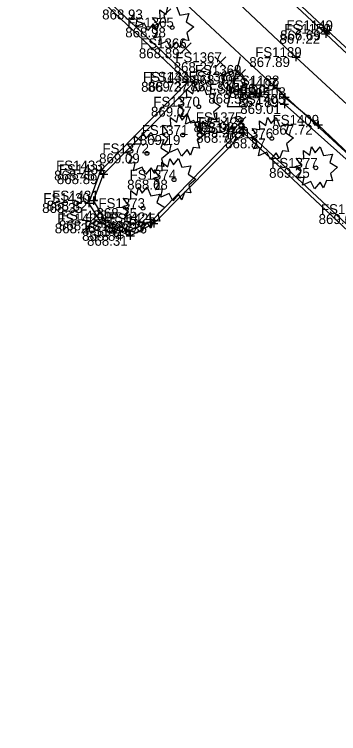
# Model space of a CAD drawing. Extents: x 1479420 to 1479833, y 379731 to 380103.
# Drawn here: x 1479671.7 to 1479710.9, y 379733.1 to 379820.1 of the extents above; entities that cross this region are included whole.
import ezdxf

# ---------------------------------------------------------------- set-up
doc = ezdxf.new("R2010")
doc.units = 0
for name, color, linetype in [('LT_X_Poles', 7, 'Continuous'), ('PV_X_Curb', 7, 'Continuous'), ('PV_X_Walk', 7, 'Continuous'), ('RD_X_Wall', 7, 'Continuous'), ('SV_X_Break_Lines', 7, 'Continuous'), ('SV_X_Random_Point', 7, 'Continuous'), ('SV_X_Shot_Marker', 7, 'Continuous'), ('SV_X_Text_Elevation', 7, 'Continuous'), ('SV_X_Text_Name', 7, 'Continuous'), ('VG_X_Cells', 7, 'Continuous')]:
    doc.layers.add(name, color=color, linetype=linetype)

msp = doc.modelspace()

# ---------------------------------------------------------------- linework, layer by layer
at = {"layer": 'LT_X_Poles'}
msp.add_lwpolyline([(1479699.003, 379814.915), (1479697.428, 379808.93), (1479699.791, 379808.93)], dxfattribs=at)
msp.add_circle((1479698.216, 379811.961), 1.3, dxfattribs=at)
at = {"layer": 'PV_X_Curb'}
for points in [[(1479752.341, 379756.82), (1479734.895, 379773.493), (1479717.229, 379789.662), (1479699.298, 379806.401), (1479688.16, 379794.934), (1479685.526, 379793.897), (1479682.733, 379795.157), (1479681.263, 379797.549), (1479682.493, 379800.746), (1479693.462, 379811.911), (1479675.554, 379828.75), (1479655.832, 379847.057), (1479640.191, 379861.808), (1479628.558, 379849), (1479624.614, 379847.663), (1479622.46, 379848.585), (1479618.996, 379850.857), (1479611.825, 379854.437), (1479601.319, 379856.891), (1479590.521, 379858.038)], [(1479751.933, 379756.628), (1479734.447, 379772.976), (1479716.701, 379789.463), (1479699.4, 379805.742), (1479688.561, 379794.786), (1479685.717, 379793.294), (1479682.291, 379794.8), (1479680.73, 379797.254), (1479682.169, 379801.189), (1479692.652, 379811.907), (1479675.183, 379828.391), (1479655.51, 379846.682), (1479640.151, 379860.926), (1479629.134, 379848.869), (1479624.571, 379847.215), (1479622.228, 379847.911), (1479618.757, 379850.398), (1479611.519, 379853.97), (1479601.347, 379856.369), (1479590.364, 379857.442)], [(1479667.239, 379857.122), (1479681.024, 379844.208), (1479695.135, 379830.978), (1479709.331, 379817.708), (1479723.729, 379804.193), (1479729.719, 379798.6), (1479748.963, 379780.548), (1479759.065, 379771.485), (1479760.185, 379770.473), (1479774.837, 379758.13), (1479787.835, 379747.16), (1479799.962, 379737.109), (1479801.3, 379736.045)], [(1479667.529, 379857.521), (1479681.356, 379844.557), (1479695.384, 379831.416), (1479709.512, 379818.131), (1479724.003, 379804.728), (1479730.662, 379798.272), (1479750.68, 379779.69), (1479759.253, 379771.893), (1479760.555, 379770.78), (1479775.03, 379758.526), (1479788.183, 379747.585), (1479800.537, 379737.251), (1479801.677, 379736.292)]]:
    msp.add_lwpolyline(points, dxfattribs=at)
at = {"layer": 'PV_X_Walk'}
for points in [[(1479760.141, 379765.373), (1479756.862, 379768.221), (1479747.096, 379776.51), (1479736.047, 379786.698), (1479722.324, 379799.574), (1479705.728, 379814.894), (1479685.769, 379833.708), (1479660.411, 379857.395)], [(1479801.031, 379735.954), (1479794.804, 379736.123), (1479792.191, 379733.142), (1479782.769, 379741.06), (1479767.055, 379754.294), (1479759.061, 379761.026), (1479757.309, 379762.481), (1479754.256, 379765.105), (1479744.261, 379773.561), (1479732.859, 379783.688), (1479719.35, 379796.384), (1479703.027, 379811.462), (1479682.443, 379830.686), (1479657.296, 379854.468)]]:
    msp.add_lwpolyline(points, dxfattribs=at)
at = {"layer": 'RD_X_Wall'}
msp.add_lwpolyline([(1479756.217, 379756.164), (1479757.574, 379758.774), (1479757.809, 379760.44), (1479756.184, 379761.773), (1479753.461, 379764.22), (1479749.272, 379767.89), (1479743.159, 379773.169), (1479734.585, 379781.475), (1479724.018, 379791.188), (1479717.004, 379797.909), (1479704.341, 379809.227)], dxfattribs=at)
at = {"layer": 'SV_X_Break_Lines'}
msp.add_lwpolyline([(1479700.791, 379810.474), (1479703.421, 379811.158), (1479704.398, 379810.048), (1479708.429, 379806.713), (1479717.526, 379798.095), (1479729.107, 379786.809), (1479738.375, 379778.753), (1479747.99, 379770.392), (1479758.225, 379761.836), (1479757.039, 379755.523)], dxfattribs=at)
at = {"layer": 'SV_X_Random_Point'}
for p, q in [((1479691.739, 379815.289), (1479693.073, 379816.624)), ((1479691.739, 379816.624), (1479693.073, 379815.289)), ((1479695.916, 379813.611), (1479697.25, 379814.946)), ((1479695.916, 379814.946), (1479697.25, 379813.611)), ((1479698.288, 379812.077), (1479699.622, 379813.412)), ((1479698.288, 379813.412), (1479699.622, 379812.077)), ((1479698.353, 379806.36), (1479699.687, 379807.695)), ((1479698.353, 379807.695), (1479699.687, 379806.36))]:
    msp.add_line(p, q, dxfattribs=at)
at = {"layer": 'SV_X_Shot_Marker'}
for p, q in [((1479709.512, 379818.631), (1479709.512, 379817.631)), ((1479708.831, 379817.708), (1479709.831, 379817.708)), ((1479709.012, 379818.131), (1479710.012, 379818.131)), ((1479709.331, 379818.208), (1479709.331, 379817.208)), ((1479709.331, 379817.708), (1479709.331, 379817.708)), ((1479709.512, 379818.131), (1479709.512, 379818.131)), ((1479705.728, 379815.394), (1479705.728, 379814.394)), ((1479705.228, 379814.894), (1479706.228, 379814.894)), ((1479705.728, 379814.894), (1479705.728, 379814.894)), ((1479692.152, 379811.907), (1479693.152, 379811.907)), ((1479692.652, 379812.407), (1479692.652, 379811.407)), ((1479692.652, 379811.907), (1479692.652, 379811.907)), ((1479692.962, 379811.911), (1479693.962, 379811.911)), ((1479693.462, 379812.411), (1479693.462, 379811.411)), ((1479693.462, 379811.911), (1479693.462, 379811.911)), ((1479703.027, 379811.962), (1479703.027, 379810.962)), ((1479703.421, 379811.658), (1479703.421, 379810.658)), ((1479700.791, 379810.974), (1479700.791, 379809.974)), ((1479702.527, 379811.462), (1479703.527, 379811.462)), ((1479702.921, 379811.158), (1479703.921, 379811.158)), ((1479703.027, 379811.462), (1479703.027, 379811.462)), ((1479703.421, 379811.158), (1479703.421, 379811.158)), ((1479700.291, 379810.474), (1479701.291, 379810.474)), ((1479700.791, 379810.474), (1479700.791, 379810.474)), ((1479703.898, 379810.048), (1479704.898, 379810.048)), ((1479704.398, 379810.548), (1479704.398, 379809.548)), ((1479704.398, 379810.048), (1479704.398, 379810.048)), ((1479703.841, 379809.227), (1479704.841, 379809.227)), ((1479704.341, 379809.727), (1479704.341, 379808.727)), ((1479704.341, 379809.227), (1479704.341, 379809.227)), ((1479698.798, 379806.401), (1479699.798, 379806.401)), ((1479699.298, 379806.901), (1479699.298, 379805.901)), ((1479699.298, 379806.401), (1479699.298, 379806.401)), ((1479707.929, 379806.713), (1479708.929, 379806.713)), ((1479708.429, 379807.213), (1479708.429, 379806.213)), ((1479708.429, 379806.713), (1479708.429, 379806.713)), ((1479698.9, 379805.742), (1479699.9, 379805.742)), ((1479699.4, 379806.242), (1479699.4, 379805.242)), ((1479699.4, 379805.742), (1479699.4, 379805.742)), ((1479681.669, 379801.189), (1479682.669, 379801.189)), ((1479682.169, 379801.689), (1479682.169, 379800.689)), ((1479682.169, 379801.189), (1479682.169, 379801.189)), ((1479682.493, 379801.246), (1479682.493, 379800.246)), ((1479681.993, 379800.746), (1479682.993, 379800.746)), ((1479682.493, 379800.746), (1479682.493, 379800.746)), ((1479680.73, 379797.754), (1479680.73, 379796.754)), ((1479681.263, 379798.049), (1479681.263, 379797.049)), ((1479680.23, 379797.254), (1479681.23, 379797.254)), ((1479680.73, 379797.254), (1479680.73, 379797.254)), ((1479680.763, 379797.549), (1479681.763, 379797.549)), ((1479681.263, 379797.549), (1479681.263, 379797.549)), ((1479682.233, 379795.157), (1479683.233, 379795.157)), ((1479682.291, 379795.3), (1479682.291, 379794.3)), ((1479682.733, 379795.657), (1479682.733, 379794.657)), ((1479682.733, 379795.157), (1479682.733, 379795.157)), ((1479688.16, 379795.434), (1479688.16, 379794.434)), ((1479688.561, 379795.286), (1479688.561, 379794.286)), ((1479681.791, 379794.8), (1479682.791, 379794.8)), ((1479682.291, 379794.8), (1479682.291, 379794.8)), ((1479685.526, 379794.397), (1479685.526, 379793.397)), ((1479687.66, 379794.934), (1479688.66, 379794.934)), ((1479688.061, 379794.786), (1479689.061, 379794.786)), ((1479688.16, 379794.934), (1479688.16, 379794.934)), ((1479688.561, 379794.786), (1479688.561, 379794.786)), ((1479685.026, 379793.897), (1479686.026, 379793.897)), ((1479685.526, 379793.897), (1479685.526, 379793.897)), ((1479685.717, 379793.794), (1479685.717, 379792.794)), ((1479685.217, 379793.294), (1479686.217, 379793.294)), ((1479685.717, 379793.294), (1479685.717, 379793.294))]:
    msp.add_line(p, q, dxfattribs=at)
at = {"layer": 'VG_X_Cells'}
for points in [[(1479690.613, 379820.712), (1479689.757, 379819.977), (1479690.007, 379819.063), (1479689.253, 379819.132), (1479688.928, 379818.218), (1479688.5, 379818.91), (1479687.822, 379818.093), (1479687.393, 379818.98), (1479686.373, 379818.55), (1479686.565, 379819.492), (1479685.753, 379819.408), (1479686.227, 379820.198)], [(1479691.298, 379821.026), (1479691.713, 379819.972), (1479692.805, 379820.152), (1479692.466, 379819.141), (1479693.411, 379818.546), (1479692.555, 379817.811), (1479692.805, 379816.897), (1479692.051, 379816.966), (1479691.726, 379816.052), (1479691.298, 379816.744), (1479690.62, 379815.927), (1479690.191, 379816.814), (1479689.171, 379816.384), (1479689.363, 379817.326), (1479688.551, 379817.242), (1479689.025, 379818.032), (1479688.256, 379818.601), (1479688.995, 379818.864), (1479688.388, 379819.667), (1479689.32, 379819.557), (1479689.29, 379820.596), (1479690.043, 379820.027), (1479690.25, 379821.012)], [(1479693.906, 379810.711), (1479694.511, 379811.446), (1479694.926, 379810.393), (1479696.018, 379810.573), (1479695.679, 379809.561), (1479696.624, 379808.966), (1479695.768, 379808.231), (1479696.018, 379807.318), (1479695.264, 379807.386), (1479694.939, 379806.473), (1479694.511, 379807.164), (1479693.833, 379806.348), (1479693.404, 379807.234), (1479692.384, 379806.804), (1479692.576, 379807.746), (1479691.764, 379807.663), (1479692.238, 379808.453), (1479691.469, 379809.021), (1479692.208, 379809.284), (1479691.601, 379810.088), (1479692.533, 379809.978), (1479692.503, 379811.016), (1479693.256, 379810.448), (1479693.463, 379811.433), (1479693.906, 379810.711)], [(1479691.972, 379807.288), (1479692.577, 379808.023), (1479692.992, 379806.969), (1479694.084, 379807.149), (1479693.745, 379806.138), (1479694.69, 379805.543), (1479693.834, 379804.808), (1479694.084, 379803.894), (1479693.33, 379803.963), (1479693.005, 379803.049), (1479692.577, 379803.741), (1479691.899, 379802.924), (1479691.47, 379803.811), (1479690.45, 379803.381), (1479690.642, 379804.323), (1479689.83, 379804.239), (1479690.304, 379805.029), (1479689.535, 379805.598), (1479690.274, 379805.861), (1479689.667, 379806.664), (1479690.599, 379806.554), (1479690.569, 379807.593), (1479691.322, 379807.024), (1479691.529, 379808.009), (1479691.972, 379807.288)], [(1479702.73, 379806.878), (1479703.335, 379807.613), (1479703.75, 379806.559), (1479704.842, 379806.739), (1479704.503, 379805.728), (1479705.448, 379805.133), (1479704.592, 379804.398), (1479704.842, 379803.484), (1479704.088, 379803.553), (1479703.763, 379802.639), (1479703.335, 379803.331), (1479702.657, 379802.514), (1479702.228, 379803.401), (1479701.208, 379802.971), (1479701.4, 379803.913), (1479700.588, 379803.829), (1479701.062, 379804.619), (1479700.293, 379805.188), (1479701.032, 379805.451), (1479700.425, 379806.254), (1479701.357, 379806.144), (1479701.327, 379807.183), (1479702.08, 379806.614), (1479702.287, 379807.599), (1479702.73, 379806.878)], [(1479687.646, 379805.067), (1479688.251, 379805.802), (1479688.666, 379804.749), (1479689.758, 379804.929), (1479689.419, 379803.917), (1479690.364, 379803.322), (1479689.508, 379802.587), (1479689.758, 379801.674), (1479689.004, 379801.742), (1479688.679, 379800.829), (1479688.251, 379801.521), (1479687.573, 379800.704), (1479687.144, 379801.591), (1479686.124, 379801.161), (1479686.316, 379802.102), (1479685.504, 379802.019), (1479685.978, 379802.809), (1479685.209, 379803.377), (1479685.948, 379803.641), (1479685.341, 379804.444), (1479686.273, 379804.334), (1479686.243, 379805.372), (1479686.996, 379804.804), (1479687.203, 379805.789), (1479687.646, 379805.067)], [(1479708.046, 379803.323), (1479708.651, 379804.058), (1479709.066, 379803.004), (1479710.158, 379803.184), (1479709.819, 379802.173), (1479710.764, 379801.578), (1479709.908, 379800.843), (1479710.158, 379799.929), (1479709.404, 379799.998), (1479709.079, 379799.084), (1479708.651, 379799.776), (1479707.973, 379798.959), (1479707.544, 379799.846), (1479706.524, 379799.416), (1479706.716, 379800.358), (1479705.904, 379800.274), (1479706.378, 379801.064), (1479705.609, 379801.633), (1479706.348, 379801.896), (1479705.741, 379802.699), (1479706.673, 379802.589), (1479706.643, 379803.628), (1479707.396, 379803.059), (1479707.603, 379804.044), (1479708.046, 379803.323)], [(1479690.923, 379801.895), (1479691.528, 379802.63), (1479691.943, 379801.576), (1479693.035, 379801.756), (1479692.696, 379800.745), (1479693.641, 379800.15), (1479692.785, 379799.415), (1479693.035, 379798.501), (1479692.281, 379798.57), (1479691.956, 379797.656), (1479691.528, 379798.348), (1479690.85, 379797.531), (1479690.421, 379798.418), (1479689.401, 379797.988), (1479689.593, 379798.93), (1479688.781, 379798.846), (1479689.255, 379799.636), (1479688.486, 379800.205), (1479689.225, 379800.468), (1479688.618, 379801.271), (1479689.55, 379801.161), (1479689.52, 379802.2), (1479690.273, 379801.631), (1479690.48, 379802.616), (1479690.923, 379801.895)], [(1479687.172, 379798.455), (1479687.777, 379799.19), (1479688.192, 379798.136), (1479689.284, 379798.316), (1479688.945, 379797.305), (1479689.89, 379796.71), (1479689.034, 379795.975), (1479689.284, 379795.061), (1479688.53, 379795.13), (1479688.205, 379794.216), (1479687.777, 379794.908), (1479687.099, 379794.091), (1479686.67, 379794.978), (1479685.65, 379794.548), (1479685.842, 379795.49), (1479685.03, 379795.406), (1479685.504, 379796.196), (1479684.735, 379796.765), (1479685.474, 379797.028), (1479684.867, 379797.831), (1479685.799, 379797.721), (1479685.769, 379798.76), (1479686.522, 379798.191), (1479686.729, 379799.176), (1479687.172, 379798.455)]]:
    msp.add_lwpolyline(points, dxfattribs=at)
for centre in [(1479690.777, 379818.481), (1479693.99, 379808.902), (1479692.056, 379805.478), (1479702.814, 379805.068), (1479687.73, 379803.258), (1479708.13, 379801.513), (1479691.007, 379800.085), (1479687.256, 379796.645)]:
    msp.add_circle(centre, 0.23, dxfattribs=at)

# ---------------------------------------------------------------- texts
at = {"layer": 'SV_X_Text_Elevation'}
for s, p in [('868.93', (1479682.321, 379819.447)), ('868.98', (1479685.109, 379817.281)), ('867.22', (1479703.738, 379816.508)), ('866.69', (1479703.824, 379816.931)), ('868.89', (1479686.756, 379814.757)), ('868.27', (1479690.961, 379813.079)), ('867.89', (1479700.097, 379813.694)), ('868.09', (1479693.192, 379811.545)), ('868.73', (1479687.03, 379810.707)), ('869.27', (1479687.821, 379810.711)), ('868.31', (1479692.99, 379810.762)), ('868.00', (1479697.169, 379810.262)), ('868.05', (1479697.667, 379809.958)), ('868.58', (1479695.141, 379809.274)), ('867.89', (1479698.767, 379808.848)), ('869.01', (1479699.002, 379808.027)), ('869.07', (1479688.218, 379807.701)), ('868.93', (1479693.361, 379805.827)), ('869.27', (1479693.657, 379805.201)), ('867.72', (1479702.836, 379805.513)), ('868.70', (1479693.674, 379804.542)), ('869.19', (1479686.861, 379804.278)), ('868.87', (1479697.174, 379803.868)), ('869.09', (1479681.949, 379802.057)), ('868.45', (1479676.519, 379799.989)), ('869.25', (1479702.49, 379800.313)), ('868.89', (1479676.843, 379799.546)), ('868.68', (1479685.339, 379798.885)), ('868.35', (1479675.071, 379796.054)), ('868.82', (1479675.632, 379796.349)), ('868.75', (1479681.635, 379795.445)), ('868.78', (1479677.102, 379793.957)), ('869.65', (1479708.471, 379794.721)), ('868.26', (1479676.594, 379793.6)), ('868.95', (1479682.501, 379793.734)), ('868.36', (1479682.826, 379793.586)), ('868.84', (1479679.895, 379792.697)), ('868.31', (1479680.491, 379792.094))]:
    msp.add_text(s, height=1.2, dxfattribs=at).set_placement(p)
at = {"layer": 'SV_X_Text_Name'}
for s, p in [('FS1365', (1479685.355, 379818.481)), ('FS1150', (1479704.315, 379817.708)), ('FS1149', (1479704.581, 379818.131)), ('FS1366', (1479686.908, 379815.957)), ('FS1189', (1479700.807, 379814.894)), ('FS1367', (1479691.16, 379814.279)), ('FS1369', (1479693.523, 379812.745)), ('FS1434', (1479687.248, 379811.907)), ('FS1435', (1479688.049, 379811.911)), ('FS1368', (1479692.784, 379811.962)), ('FS1188', (1479698.106, 379811.462)), ('FS1406', (1479695.208, 379810.474)), ('FS1407', (1479697.913, 379811.158)), ('FS1408', (1479698.881, 379810.048)), ('FS1370', (1479688.502, 379808.901)), ('FS1405', (1479698.833, 379809.227)), ('FS1375', (1479693.635, 379807.027)), ('FS1423', (1479693.923, 379806.401)), ('FS1409', (1479702.912, 379806.713)), ('FS1371', (1479687.106, 379805.478)), ('FS1422', (1479694.034, 379805.742)), ('FS1376', (1479697.355, 379805.068)), ('FS1372', (1479682.356, 379803.257)), ('FS1433', (1479676.756, 379801.189)), ('FS1377', (1479702.746, 379801.513)), ('FS1432', (1479677.089, 379800.746)), ('FS1374', (1479685.633, 379800.085)), ('FS1431', (1479676.284, 379797.549)), ('FS1430', (1479675.213, 379797.254)), ('FS1373', (1479681.872, 379796.645)), ('FS1378', (1479708.755, 379795.921)), ('FS1429', (1479676.906, 379794.8)), ('FS1428', (1479677.348, 379795.157)), ('FS1424', (1479682.794, 379794.934)), ('FS1425', (1479683.186, 379794.786)), ('FS1427', (1479680.151, 379793.897)), ('FS1426', (1479680.266, 379793.294))]:
    msp.add_text(s, height=1.2, dxfattribs=at).set_placement(p)

doc.saveas('drawing.dxf')
